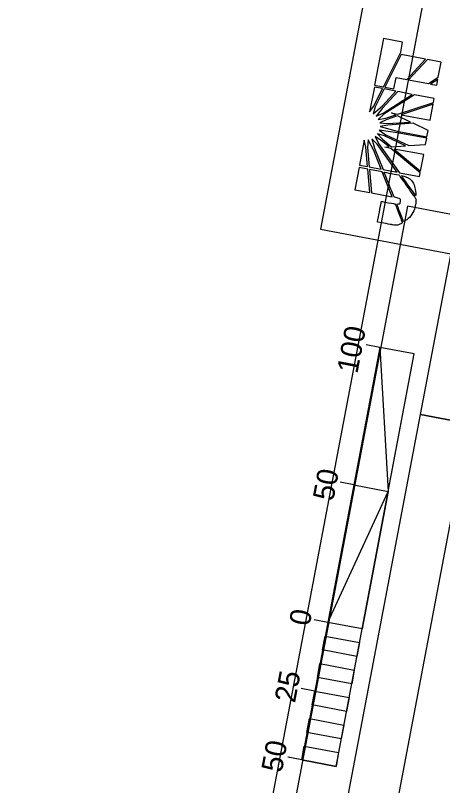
# Model space of a CAD drawing. Extents: x 1615680 to 1617075, y 898420 to 901168.
# Drawn here: x 1616695.7 to 1616848.5, y 900488.2 to 900763.4 of the extents above; entities that cross this region are included whole.
import ezdxf

# ---------------------------------------------------------------- set-up
doc = ezdxf.new("R2010")
doc.units = 0
for name, color, linetype in [('Default', 7, 'Continuous'), ('DEV BORDER CELL', 7, 'Continuous'), ('Scratch_Level_0', 7, 'Continuous'), ('Sheet Clip Boundary CELL', 7, 'Continuous'), ('Sheet Data Field CELL', 7, 'Continuous'), ('Sheet Plan CELL', 7, 'Continuous'), ('Sheet Title CELL', 7, 'Continuous')]:
    doc.layers.add(name, color=color, linetype=linetype)

msp = doc.modelspace()

# ---------------------------------------------------------------- linework, layer by layer
at = {"layer": 'Default'}
for p, q in [((1616827.31, 900755.17), (1616824.15, 900738.45)), ((1616834.16, 900753.88), (1616827.31, 900755.17)), ((1616833.49, 900750.32), (1616834.16, 900753.88)), ((1616827.31, 900737.85), (1616833.49, 900750.32)), ((1616833.63, 900749.42), (1616827.78, 900737.76)), ((1616842.41, 900747.76), (1616833.63, 900749.42)), ((1616835.63, 900740.51), (1616842.41, 900747.76)), ((1616843.03, 900747.65), (1616836.29, 900740.38)), ((1616847.97, 900746.71), (1616843.03, 900747.65)), ((1616846.95, 900741.32), (1616847.97, 900746.71)), ((1616831.04, 900737.15), (1616831.81, 900741.23)), ((1616831.81, 900741.23), (1616835.63, 900740.51)), ((1616836.29, 900740.38), (1616843.4, 900739.04)), ((1616843.4, 900739.04), (1616846.95, 900741.32)), ((1616846.8, 900740.53), (1616844.18, 900738.89)), ((1616846.41, 900738.47), (1616846.8, 900740.53)), ((1616824.07, 900737.82), (1616822.36, 900729.01)), ((1616826.93, 900737.28), (1616824.07, 900737.82)), ((1616824.15, 900738.45), (1616827.22, 900737.87)), ((1616827.22, 900737.87), (1616827.31, 900737.85)), ((1616827.78, 900737.76), (1616827.84, 900737.75)), ((1616827.84, 900737.75), (1616831.04, 900737.15)), ((1616844.18, 900738.89), (1616846.41, 900738.47)), ((1616823.84, 900731.04), (1616826.93, 900737.28)), ((1616827.54, 900737.17), (1616824.37, 900730.71)), ((1616832.45, 900736.19), (1616826.81, 900730.17)), ((1616826.95, 900731.13), (1616831.74, 900736.32)), ((1616827.18, 900728.51), (1616837.54, 900735.22)), ((1616838.37, 900735.07), (1616827.5, 900728.08)), ((1616831.74, 900736.32), (1616827.54, 900737.17)), ((1616837.54, 900735.22), (1616832.45, 900736.19)), ((1616845.51, 900733.72), (1616838.37, 900735.07)), ((1616832.52, 900728.14), (1616845.25, 900732.31)), ((1616845.25, 900732.31), (1616845.51, 900733.72)), ((1616822.36, 900729.01), (1616823.84, 900731.04)), ((1616823.59, 900728.31), (1616826.95, 900731.13)), ((1616824.37, 900730.71), (1616823.59, 900728.31)), ((1616826.81, 900730.17), (1616824.69, 900727.39)), ((1616845.08, 900731.66), (1616833.66, 900727.92)), ((1616844.01, 900725.97), (1616845.08, 900731.66)), ((1616824.69, 900727.39), (1616827.18, 900728.51)), ((1616827.5, 900728.08), (1616825.48, 900726.27)), ((1616825.48, 900726.27), (1616828.21, 900726.76)), ((1616828.21, 900726.76), (1616831.69, 900727.87)), ((1616832.4, 900727.52), (1616828.28, 900726.16)), ((1616831.69, 900727.87), (1616830.19, 900728.58)), ((1616830.19, 900728.58), (1616832.52, 900728.14)), ((1616836.99, 900725.33), (1616832.4, 900727.52)), ((1616833.66, 900727.92), (1616844.01, 900725.97)), ((1616828.28, 900726.16), (1616825.97, 900725.01)), ((1616825.97, 900725.01), (1616828.57, 900724.79)), ((1616828.83, 900724.24), (1616826.09, 900723.67)), ((1616828.57, 900724.79), (1616836.99, 900725.33)), ((1616837.99, 900724.87), (1616828.83, 900724.24)), ((1616843.31, 900722.28), (1616837.99, 900724.87)), ((1616825.24, 900721.11), (1616826.96, 900719.15)), ((1616827.65, 900720.42), (1616825.24, 900721.11)), ((1616832.18, 900721.51), (1616825.84, 900722.36)), ((1616825.84, 900722.36), (1616828.18, 900720.79)), ((1616826.09, 900723.67), (1616832.28, 900722.08)), ((1616842.79, 900719.51), (1616832.18, 900721.51)), ((1616832.28, 900722.08), (1616842.89, 900720.07)), ((1616842.89, 900720.07), (1616843.31, 900722.28)), ((1616820.45, 900718.87), (1616818.76, 900709.92)), ((1616821.03, 900716.4), (1616820.45, 900718.87)), ((1616821.82, 900718.94), (1616821.64, 900716.28)), ((1616823.88, 900715.14), (1616821.82, 900718.94)), ((1616825.04, 900717.42), (1616823.18, 900719.36)), ((1616823.18, 900719.36), (1616824.14, 900716.04)), ((1616824.31, 900720.1), (1616825.54, 900717.68)), ((1616826.67, 900718.65), (1616824.31, 900720.1)), ((1616829.39, 900716.41), (1616826.67, 900718.65)), ((1616826.96, 900719.15), (1616830.18, 900716.49)), ((1616835.2, 900716.86), (1616827.65, 900720.42)), ((1616828.18, 900720.79), (1616836.35, 900716.92)), ((1616842.37, 900717.33), (1616842.79, 900719.51)), ((1616821.61, 900709.38), (1616821.03, 900716.4)), ((1616821.64, 900716.28), (1616822.22, 900709.27)), ((1616824.14, 900716.04), (1616827.22, 900708.32)), ((1616832.19, 900707.38), (1616825.04, 900717.42)), ((1616825.54, 900717.68), (1616833.03, 900707.22)), ((1616827.87, 900716.29), (1616829.39, 900716.41)), ((1616829.97, 900715.89), (1616827.87, 900716.29)), ((1616840.5, 900707.17), (1616829.97, 900715.89)), ((1616830.18, 900716.49), (1616835.2, 900716.86)), ((1616841.73, 900713.72), (1616831.12, 900715.68)), ((1616831.12, 900715.68), (1616840.61, 900707.79)), ((1616836.35, 900716.92), (1616842.37, 900717.33)), ((1616826.53, 900708.45), (1616823.88, 900715.14)), ((1616840.61, 900707.79), (1616841.73, 900713.72)), ((1616818.64, 900709.09), (1616817.14, 900701.13)), ((1616821.71, 900708.51), (1616818.64, 900709.09)), ((1616818.76, 900709.92), (1616821.61, 900709.38)), ((1616822.41, 900700.13), (1616821.71, 900708.51)), ((1616822.22, 900709.27), (1616826.53, 900708.45)), ((1616826.9, 900707.53), (1616822.29, 900708.4)), ((1616822.29, 900708.4), (1616823.02, 900700.02)), ((1616830.44, 900698.62), (1616826.9, 900707.53)), ((1616827.22, 900708.32), (1616832.19, 900707.38)), ((1616833.03, 900707.22), (1616840.25, 900705.86)), ((1616840.25, 900705.86), (1616840.5, 900707.17)), ((1616817.14, 900701.13), (1616822.41, 900700.13)), ((1616823.02, 900700.02), (1616830.44, 900698.62))]:
    msp.add_line(p, q, dxfattribs=at)
for points in [[(1616827.78, 900737.76), (1616827.84, 900737.75), (1616831.04, 900737.15), (1616831.81, 900741.23), (1616835.63, 900740.51), (1616842.41, 900747.76), (1616833.63, 900749.42), (1616827.78, 900737.76)], [(1616836.29, 900740.38), (1616843.4, 900739.04), (1616846.95, 900741.32), (1616847.97, 900746.71), (1616843.03, 900747.65), (1616836.29, 900740.38), (1616836.29, 900740.38)], [(1616846.41, 900738.47), (1616846.41, 900738.47), (1616846.8, 900740.53), (1616844.18, 900738.89), (1616846.41, 900738.47)], [(1616823.84, 900731.04), (1616826.93, 900737.28), (1616824.07, 900737.82), (1616822.36, 900729.01), (1616823.84, 900731.04)], [(1616823.59, 900728.31), (1616826.95, 900731.13), (1616831.74, 900736.32), (1616827.54, 900737.17), (1616824.37, 900730.71), (1616823.59, 900728.31)], [(1616824.69, 900727.39), (1616827.18, 900728.51), (1616837.54, 900735.22), (1616832.45, 900736.19), (1616826.81, 900730.17), (1616824.69, 900727.39)], [(1616825.48, 900726.27), (1616828.21, 900726.76), (1616831.69, 900727.87), (1616830.19, 900728.58), (1616832.52, 900728.14), (1616845.25, 900732.31), (1616845.51, 900733.72), (1616838.37, 900735.07), (1616827.5, 900728.08), (1616825.48, 900726.27)], [(1616844.01, 900725.97), (1616845.08, 900731.66), (1616833.66, 900727.92), (1616844.01, 900725.97)], [(1616825.97, 900725.01), (1616828.57, 900724.79), (1616836.99, 900725.33), (1616832.4, 900727.52), (1616828.28, 900726.16), (1616825.97, 900725.01)], [(1616826.09, 900723.67), (1616832.28, 900722.08), (1616842.89, 900720.07), (1616843.31, 900722.28), (1616837.99, 900724.87), (1616828.83, 900724.24), (1616826.09, 900723.67)], [(1616825.24, 900721.11), (1616826.96, 900719.15), (1616830.18, 900716.49), (1616835.2, 900716.86), (1616827.65, 900720.42), (1616825.24, 900721.11)], [(1616828.18, 900720.79), (1616836.35, 900716.92), (1616842.37, 900717.33), (1616842.79, 900719.51), (1616832.18, 900721.51), (1616825.84, 900722.36), (1616828.18, 900720.79)], [(1616821.03, 900716.4), (1616820.45, 900718.87), (1616818.76, 900709.92), (1616821.61, 900709.38), (1616821.03, 900716.4)], [(1616822.22, 900709.27), (1616826.53, 900708.45), (1616823.88, 900715.14), (1616821.82, 900718.94), (1616821.64, 900716.28), (1616822.22, 900709.27)], [(1616827.22, 900708.32), (1616832.19, 900707.38), (1616825.04, 900717.42), (1616823.18, 900719.36), (1616824.14, 900716.04), (1616827.22, 900708.32)], [(1616824.31, 900720.1), (1616825.54, 900717.68), (1616833.03, 900707.22), (1616840.25, 900705.86), (1616840.5, 900707.17), (1616829.97, 900715.89), (1616827.87, 900716.29), (1616829.39, 900716.41), (1616826.67, 900718.65), (1616824.31, 900720.1)], [(1616840.61, 900707.79), (1616841.73, 900713.72), (1616831.12, 900715.68), (1616840.61, 900707.79)], [(1616822.41, 900700.13), (1616821.71, 900708.51), (1616818.64, 900709.09), (1616817.14, 900701.13), (1616822.41, 900700.13)], [(1616830.44, 900698.62), (1616826.9, 900707.53), (1616822.29, 900708.4), (1616823.02, 900700.02), (1616830.44, 900698.62)]]:
    msp.add_lwpolyline(points, dxfattribs=at)
for points in [[(1616833.44, 900696.87), (1616833.35, 900696.4), (1616833.01, 900696.04), (1616832.1, 900696.03), (1616832.1, 900696.03), (1616834.55, 900689.66), (1616834.55, 900689.66), (1616836.73, 900691.07), (1616838.37, 900693.67), (1616838.81, 900696.04), (1616838.93, 900696.66), (1616838.97, 900697.14), (1616838.96, 900697.82), (1616838.96, 900697.82), (1616832.91, 900706.39), (1616832.91, 900706.39), (1616832.91, 900706.39), (1616827.55, 900707.4), (1616827.55, 900707.4), (1616827.55, 900707.4), (1616831.11, 900698.49), (1616831.11, 900698.49), (1616833.11, 900698.11), (1616833.56, 900697.52), (1616833.44, 900696.87)], [(1616833.44, 900696.87), (1616833.35, 900696.4), (1616833.01, 900696.04), (1616832.1, 900696.03), (1616832.1, 900696.03), (1616834.55, 900689.66), (1616834.55, 900689.66), (1616836.73, 900691.07), (1616838.37, 900693.67), (1616838.81, 900696.04), (1616838.93, 900696.66), (1616838.97, 900697.14), (1616838.96, 900697.82), (1616838.96, 900697.82), (1616832.91, 900706.39), (1616832.91, 900706.39), (1616832.91, 900706.39), (1616827.55, 900707.4), (1616827.55, 900707.4), (1616827.55, 900707.4), (1616831.11, 900698.49), (1616831.11, 900698.49), (1616833.11, 900698.11), (1616833.56, 900697.52), (1616833.44, 900696.87)], [(1616833.75, 900706.23), (1616833.75, 900706.23), (1616838.97, 900698.83), (1616838.97, 900698.83), (1616838.8, 900702), (1616837.36, 900705.4), (1616833.75, 900706.23)], [(1616833.75, 900706.23), (1616833.75, 900706.23), (1616838.97, 900698.83), (1616838.97, 900698.83), (1616838.8, 900702), (1616837.36, 900705.4), (1616833.75, 900706.23)], [(1616826.59, 900696.98), (1616826.59, 900696.98), (1616825.2, 900689.61), (1616825.2, 900689.61), (1616825.2, 900689.61), (1616829.81, 900688.74), (1616829.81, 900688.74), (1616829.81, 900688.74), (1616830.29, 900688.65), (1616830.29, 900688.65), (1616831.74, 900688.38), (1616832.97, 900688.64), (1616834.09, 900689.29), (1616834.09, 900689.29), (1616831.55, 900696.04), (1616831.46, 900696.06), (1616831.46, 900696.06), (1616826.59, 900696.98), (1616826.59, 900696.98)], [(1616826.59, 900696.98), (1616826.59, 900696.98), (1616825.2, 900689.61), (1616825.2, 900689.61), (1616825.2, 900689.61), (1616829.81, 900688.74), (1616829.81, 900688.74), (1616829.81, 900688.74), (1616830.29, 900688.65), (1616830.29, 900688.65), (1616831.74, 900688.38), (1616832.97, 900688.64), (1616834.09, 900689.29), (1616834.09, 900689.29), (1616831.55, 900696.04), (1616831.46, 900696.06), (1616831.46, 900696.06), (1616826.59, 900696.98), (1616826.59, 900696.98)]]:
    msp.add_open_spline(points, degree=3, dxfattribs=at)
at = {"layer": 'DEV BORDER CELL'}
msp.add_line((1616829.71, 900468.75), (1616857, 900612.52), dxfattribs=at)
for points in [[(1616840.59, 900620.87), (1616861.86, 900732.87), (1616996.95, 900707.23), (1616975.68, 900595.22)], [(1616803.28, 900424.35), (1616840.59, 900620.87), (1616975.68, 900595.22), (1616938.37, 900398.7)]]:
    msp.add_lwpolyline(points, close=True, dxfattribs=at)
at = {"layer": 'Scratch_Level_0'}
msp.add_lwpolyline([(1616054.34, 901080.76), (1615793.19, 899705.33), (1616726.52, 899528.12), (1616890.46, 900391.55), (1616774.26, 900413.61), (1616871.48, 900925.61)], close=True, dxfattribs=at)
at = {"layer": 'Sheet Clip Boundary CELL'}
for points in [[(1616176.29, 901060.7), (1616848.46, 900914.27), (1616896.28, 900812.91), (1616872.94, 900688.21), (1616835.87, 900695.21), (1616753.94, 900262.18), (1616898.09, 900233.43), (1616734.79, 899562.1), (1616202.98, 899609.43), (1616198.71, 899647.14), (1615822.69, 899825.07), (1616054.34, 901080.76)], [(1616176.29, 901060.7), (1616914, 900899.99), (1616896.28, 900812.91), (1616872.94, 900688.21), (1616835.87, 900695.21), (1616753.94, 900262.18), (1616898.09, 900233.43), (1616747.89, 899480.25), (1615915.8, 899646.19), (1615751.76, 899738.03), (1615981.58, 900932.46), (1616145.94, 900899.57)]]:
    msp.add_lwpolyline(points, close=True, dxfattribs=at)
at = {"layer": 'Sheet Data Field CELL'}
for p, q in [((1616826.05, 900644.79), (1616821.13, 900645.73)), ((1616816.72, 900595.67), (1616811.82, 900596.6)), ((1616802.75, 900521.98), (1616797.83, 900522.92)), ((1616798.07, 900497.42), (1616793.17, 900498.35))]:
    msp.add_line(p, q, dxfattribs=at)
at = {"layer": 'Sheet Plan CELL'}
msp.add_lwpolyline([(1616859.19, 900973.59), (1616804.79, 900687.04), (1616851.47, 900678.18), (1616905.88, 900964.73)], close=True, dxfattribs=at)
at = {"layer": 'Sheet Title CELL'}
for p, q in [((1616826.05, 900644.78), (1616798.08, 900497.41)), ((1616826.05, 900644.78), (1616821.14, 900645.71)), ((1616838.34, 900642.45), (1616826.05, 900644.78)), ((1616810.36, 900495.08), (1616838.34, 900642.45)), ((1616816.73, 900595.66), (1616811.83, 900596.59)), ((1616816.73, 900595.66), (1616829.01, 900593.32)), ((1616807.42, 900546.53), (1616802.51, 900547.46)), ((1616804.61, 900531.8), (1616816.89, 900529.46)), ((1616802.76, 900521.97), (1616797.83, 900522.9)), ((1616798.08, 900497.41), (1616793.18, 900498.34)), ((1616798.08, 900497.41), (1616810.36, 900495.08))]:
    msp.add_line(p, q, dxfattribs=at)
for points in [[(1616826.05, 900644.78), (1616829.01, 900593.32), (1616838.34, 900642.45)], [(1616807.42, 900546.53), (1616829.01, 900593.32), (1616819.7, 900544.2)], [(1616805.54, 900536.71), (1616806.47, 900541.62), (1616818.77, 900539.29), (1616817.82, 900534.38)], [(1616803.69, 900526.88), (1616804.61, 900531.8), (1616816.89, 900529.46), (1616815.96, 900524.55)], [(1616801.82, 900517.06), (1616802.76, 900521.97), (1616815.03, 900519.64), (1616814.09, 900514.73)], [(1616799.95, 900507.23), (1616800.89, 900512.14), (1616813.17, 900509.81), (1616812.24, 900504.91)], [(1616798.08, 900497.41), (1616799.02, 900502.32), (1616811.3, 900499.99), (1616810.36, 900495.08)]]:
    msp.add_lwpolyline(points, close=True, dxfattribs=at)

# ---------------------------------------------------------------- texts
for s, p in [('100', (1616817.98, 900635.15)), ('50', (1616809.34, 900589.62)), ('0', (1616800.86, 900544.97)), ('25', (1616795.65, 900517.49)), ('50', (1616790.92, 900492.59))]:
    msp.add_text(s, height=7.5, rotation=79.2541, dxfattribs=at).set_placement(p)

doc.saveas('drawing.dxf')
